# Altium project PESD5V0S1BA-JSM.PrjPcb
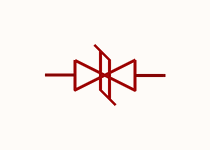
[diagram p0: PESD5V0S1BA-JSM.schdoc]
1 sheet, 1 parts. Net scope: global (net labels, ports and power ports of the same name join across sheets).

## Sheet PESD5V0S1BA-JSM.schdoc
size 127 x 101 mm

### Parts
D?  pesd5v0s1ba-jsm  [SOD-323_L1.8-W1.3-LS2.5-BI]  (value not drawn)

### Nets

Not connected (* = marked no-connect by the designer): D? 1 2

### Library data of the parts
D? = pesd5v0s1ba-jsm: 极性:双向;反向截止电压(Vrwm):5V;钳位电压:15V;峰值脉冲电流(Ipp):10A@8/20us;峰值脉冲功率(Ppp):150W@8/20us;击穿电压(VBR):7V;; Manufacturer: JSMSEMI(杰盛微); AddInBom: yes; ModelId: f9eb3c564310447fa7e5a2d35bef3787; ModelTransform: 98.425,51.181,0,0,0,0,0,0,0; Polarity: 双向; Reverse Stand-Off Voltage (Vrwm): 5V; Clamping Voltage: 15V; Voltage - Breakdown: 7V; Reverse Leakage Current (Ir): 1uA; Number of Channels: 单路; level of protection: IEC 61000-4-2; Type: ESD; Junction Capacitance: 25pF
